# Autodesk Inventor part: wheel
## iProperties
Author: E. MOSS
Created: 2001-08
Part Number: wheel
Document SubType Name: Modeling
Designer: E. MOSS
Control State: 0
Master: False
Checked Out: False
PropertySet Name: Design Tracking Control
Length Units: 11272
Angle Units: 11279
Time Units: 11290
Mass Units: 11286
Shininess: 3
Angle Display Precision: 2
Document Length Units: 11272
Document Angle Units: 11286
Document Time Units: 11279
Document Mass Units: 11290
Document Length Units Precision: 3
Document Angle Units Precision: 2
Compacted: True
PropertySet Name: _Private Model Information
Density: 0.0
Volumn: 0.0
Area: 0.0
PropertySet Name: Model Information
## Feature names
1. Revolution1
